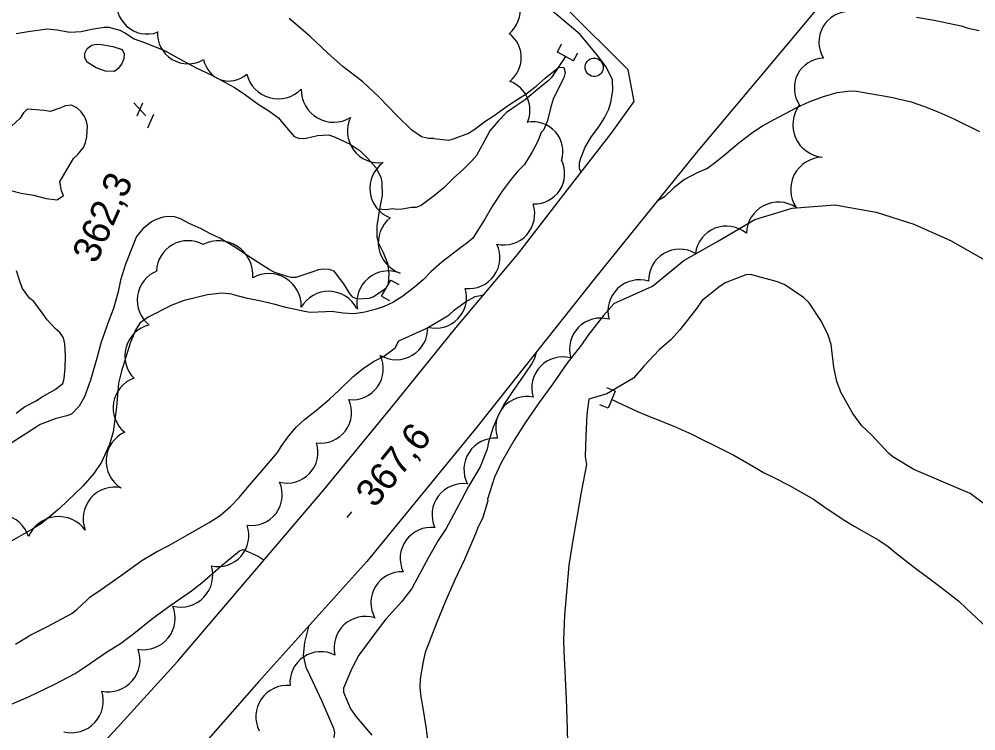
# Model space of a CAD drawing. Extents: x 287698 to 290158, y 5234163 to 5237182.
# Drawn here: x 288468 to 288572.5, y 5235628.8 to 5235706.5 of the extents above; entities that cross this region are included whole.
import ezdxf

# ---------------------------------------------------------------- set-up
doc = ezdxf.new("R2010")
doc.units = 0
for name, color, linetype in [('Niveau 19', 7, 'Continuous'), ('Niveau 2', 7, 'Continuous'), ('Niveau 21', 7, 'Continuous'), ('Niveau 26', 7, 'Continuous'), ('Niveau 3', 7, 'Continuous'), ('Niveau 36', 7, 'Continuous'), ('Niveau 4', 7, 'Continuous'), ('Niveau 44', 7, 'Continuous')]:
    doc.layers.add(name, color=color, linetype=linetype)

msp = doc.modelspace()

# ---------------------------------------------------------------- linework, layer by layer
at = {"layer": 'Niveau 19'}
msp.add_lwpolyline([(288535.15, 5235697.53), (288534.5, 5235701), (288527.62, 5235707.85), (288516.03, 5235716.32), (288501.68, 5235726.96), (288487.83, 5235737.82), (288474.98, 5235749.85), (288465.84, 5235759.9), (288456.98, 5235771.37), (288449.04, 5235782.35), (288441.52, 5235792.13)], dxfattribs=at)
at = {"layer": 'Niveau 2'}
for points in [[(288532.8, 5235699.91), (288532.14, 5235701.26), (288531.2, 5235702.52), (288529.26, 5235704.86), (288528.54, 5235705.48), (288526.2, 5235707.45)], [(288565.98, 5235706.76), (288567.92, 5235706.42), (288570.88, 5235705.81), (288571.63, 5235705.55), (288572.82, 5235705.29)], [(288513.28, 5235693.5), (288512.72, 5235693.5), (288511.94, 5235693.68), (288510.9, 5235694.4), (288509.26, 5235696), (288507.28, 5235698.06), (288505.55, 5235699.67), (288503.39, 5235701.31), (288501.73, 5235702.8), (288499.77, 5235704.67), (288497.49, 5235706.6)], [(288513.28, 5235693.5), (288514.93, 5235693.3), (288515.44, 5235693.45), (288516.99, 5235694.06), (288517.66, 5235694.44), (288518.85, 5235695.35), (288519.78, 5235695.95), (288521.54, 5235697.2), (288523.38, 5235698.39), (288524.46, 5235699.2), (288525.45, 5235700.07), (288526.94, 5235701.27), (288527.5, 5235701.25), (288527.62, 5235700.71), (288527.48, 5235700.14), (288527.18, 5235699.56), (288526.34, 5235697.81), (288526.1, 5235697.05), (288525.67, 5235695.36), (288525.25, 5235694.4), (288525.02, 5235694.17)], [(288529.39, 5235689.84), (288529.19, 5235690.18), (288529.2, 5235690.84), (288529.34, 5235691.36), (288529.81, 5235692.55), (288530.52, 5235693.72), (288531.3, 5235694.78), (288531.92, 5235695.77), (288532.39, 5235696.71), (288532.6, 5235697.48), (288532.82, 5235698.73), (288532.8, 5235699.91)], [(288543.07, 5235690.2), (288544.06, 5235690.9), (288545, 5235691.66), (288546.59, 5235693.02), (288548.13, 5235694.2), (288549.17, 5235694.87), (288550.38, 5235695.52), (288552.93, 5235696.89), (288554.34, 5235697.55), (288555.85, 5235698.1), (288557.34, 5235698.53), (288558.74, 5235698.71), (288559.43, 5235698.67), (288560.91, 5235698.43), (288563.21, 5235698.02), (288565.41, 5235697.51), (288566.88, 5235697.01), (288568.43, 5235696.39), (288570.05, 5235695.63), (288572.85, 5235694.25)], [(288525.02, 5235694.17), (288524.65, 5235693.22), (288524, 5235691.96), (288523.18, 5235690.66), (288522.46, 5235689.93), (288521.74, 5235689.06), (288520.75, 5235687.76), (288519.7, 5235686.14), (288518.86, 5235684.68), (288517.54, 5235682.63), (288517.05, 5235682.18), (288516.21, 5235681.55), (288514.18, 5235680.01), (288512.98, 5235678.93), (288512.14, 5235678.08), (288511.2, 5235677.28), (288509.92, 5235676.28), (288508.81, 5235675.6), (288507.88, 5235675.16), (288506.9, 5235674.82), (288505.77, 5235674.53), (288504.58, 5235674.35), (288503.38, 5235674.44), (288502.12, 5235674.62), (288501.51, 5235674.58), (288499.79, 5235674.5), (288499.16, 5235674.61), (288497.15, 5235675.03), (288495.96, 5235675.36), (288494.27, 5235675.77), (288492.94, 5235676.01), (288491.43, 5235676.44), (288491.43, 5235676.44)], [(288543.07, 5235690.2), (288541.96, 5235689.73), (288540.67, 5235689.03), (288539.51, 5235688.12), (288538.46, 5235687.13), (288537.68, 5235686.65)], [(288532.96, 5235675.47), (288537.15, 5235677.38), (288540.6, 5235680.16), (288544.19, 5235682.2), (288548.35, 5235684.64), (288552.4, 5235685.88), (288557.07, 5235686.26), (288561.59, 5235685.46), (288565.7, 5235684.13), (288569.7, 5235682.35), (288573.22, 5235680.35)], [(288573.56, 5235653.45), (288571.83, 5235654.73), (288569.19, 5235655.86), (288565.71, 5235657.34), (288563.39, 5235658.74), (288562.94, 5235659.15), (288561.08, 5235661.15), (288560.01, 5235662.11), (288559.04, 5235663.45), (288557.76, 5235665.74), (288557.28, 5235666.97), (288556.97, 5235668.52), (288556.69, 5235670.99), (288556.35, 5235672.03), (288555.61, 5235673.51), (288554.26, 5235675.55), (288553.66, 5235676.15), (288551.62, 5235677.53), (288550.83, 5235677.85), (288547.88, 5235678.64), (288547.37, 5235678.6), (288545.09, 5235677.72), (288544.41, 5235677.28), (288542.55, 5235675.76), (288541.99, 5235674.98), (288540.15, 5235672.61), (288539.18, 5235671.52), (288537.9, 5235670.42), (288536.22, 5235668.65), (288535.09, 5235667.32), (288532.17, 5235665.62), (288530.22, 5235665.05), (288529.99, 5235663.34), (288529.9, 5235660.99), (288529.82, 5235658.76), (288529.97, 5235657.89)], [(288491.43, 5235676.44), (288491.24, 5235676.49), (288490.14, 5235676.62), (288488.6, 5235676.43), (288486.05, 5235675.8), (288484.68, 5235675.31), (288482.12, 5235673.99), (288481.21, 5235673.33), (288480.72, 5235672.58), (288480.15, 5235671.15), (288479.18, 5235668.1), (288478.88, 5235666.78), (288478.64, 5235664.15), (288478.29, 5235661.46), (288477.89, 5235660.08), (288477.01, 5235658.15), (288476.17, 5235656.9), (288474.97, 5235655.54), (288472.42, 5235653.09), (288470.45, 5235651.45), (288469.5, 5235650.87), (288467.24, 5235649.57)], [(288509.49, 5235671.41), (288512.52, 5235672.8), (288514.98, 5235674.26), (288515.56, 5235674.78), (288516.75, 5235675.67), (288517.8, 5235676.23), (288518.74, 5235676.43)], [(288532.96, 5235675.47), (288532.94, 5235675.44), (288531.82, 5235674.17), (288530.1, 5235671.99), (288529.42, 5235670.96), (288527.83, 5235668.91), (288526.27, 5235666.69), (288524.79, 5235664.66), (288523.26, 5235662.46), (288522.07, 5235660.57), (288520.69, 5235658.16), (288519.9, 5235656.5), (288519.17, 5235654.11), (288519.19, 5235653.92)], [(288467.63, 5235638.29), (288469.3, 5235639.29), (288471.13, 5235640.19), (288473.78, 5235641.63), (288474.37, 5235642.09), (288475.37, 5235643.06), (288475.75, 5235643.4), (288476.99, 5235644.24), (288479.19, 5235645.83), (288481.43, 5235647.43), (288482.94, 5235648.34), (288484.38, 5235649.07), (288486.16, 5235650.08), (288488.78, 5235651.57), (288489.98, 5235652.33), (288491.08, 5235653.32), (288492.07, 5235654.32), (288492.94, 5235655.37), (288494.38, 5235657.04), (288496.21, 5235659.22), (288496.62, 5235659.87), (288497.45, 5235661.04), (288498.29, 5235662.02), (288499.19, 5235662.81), (288500.5, 5235663.82), (288501.92, 5235665.04), (288502.91, 5235665.97), (288504.44, 5235667.48), (288505.62, 5235668.41), (288506.79, 5235669.2), (288507.92, 5235669.77), (288509.08, 5235670.63), (288509.49, 5235671.41)], [(288524.46, 5235670.14), (288524.3, 5235669.49), (288523.98, 5235668.92), (288523.23, 5235667.79), (288522.02, 5235666.1), (288520.94, 5235664.45), (288520.28, 5235663.13), (288519.78, 5235661.98), (288519.26, 5235660.34), (288519.13, 5235659.58), (288518.34, 5235657.64)], [(288518.34, 5235657.64), (288517.08, 5235655.51), (288516.27, 5235653.96), (288514.64, 5235650.91), (288513.77, 5235649.6), (288512.72, 5235647.75), (288511.22, 5235644.97), (288510.91, 5235644.34)], [(288529.97, 5235657.89), (288529.39, 5235654.86), (288528.94, 5235652.33), (288528.5, 5235649.85), (288528.04, 5235646.91), (288527.82, 5235644.35), (288527.57, 5235641.45), (288527.45, 5235638.71), (288527.47, 5235637.5), (288527.58, 5235635.31), (288527.75, 5235632.32), (288527.8, 5235630.15), (288527.9, 5235627.63)], [(288519.19, 5235653.92), (288518.62, 5235652.01), (288518.13, 5235651.1), (288517.83, 5235650.31), (288516.66, 5235647.53), (288515.63, 5235645.36), (288514.56, 5235642.96), (288513.59, 5235640.56), (288512.33, 5235637.38), (288512.13, 5235636.4), (288511.81, 5235634.51), (288511.77, 5235633.55), (288511.88, 5235632.53), (288512.07, 5235631.49), (288512.44, 5235629.02), (288512.77, 5235626.34)], [(288465.77, 5235631.16), (288469.04, 5235632.53), (288471.83, 5235633.86), (288474.15, 5235635.06), (288475.23, 5235635.8), (288477.55, 5235637.41), (288479.08, 5235638.35), (288480.54, 5235639.43), (288482.6, 5235641.11), (288484.46, 5235642.47), (288486.85, 5235644.1), (288487.99, 5235645.02), (288489.99, 5235646.76), (288492.07, 5235648.48), (288492.49, 5235648.6), (288494.12, 5235647.89), (288494.77, 5235647.46)], [(288510.91, 5235644.34), (288509.8, 5235642.94), (288508.07, 5235641.01), (288507.18, 5235639.88), (288505.09, 5235637.08), (288504.35, 5235635.62), (288503.44, 5235633.47), (288503.45, 5235633.03), (288504.2, 5235631.2), (288504.8, 5235630.33), (288506.51, 5235628.33)], [(288499.61, 5235640.21), (288499.19, 5235638.47), (288499.03, 5235637.05), (288499.33, 5235635.77), (288499.76, 5235634.85), (288501.06, 5235632.04), (288502.33, 5235629.1), (288502.44, 5235628.59), (288502.17, 5235626.86), (288501.83, 5235624.2), (288501.88, 5235623.25), (288502.11, 5235620.09), (288501.94, 5235618.86), (288501.84, 5235618.19)]]:
    msp.add_lwpolyline(points, dxfattribs=at)
at = {"layer": 'Niveau 21'}
for points in [[(288562.24, 5235716.27), (288552.79, 5235704.84), (288541.92, 5235691.92), (288530.8, 5235678.12), (288517.95, 5235661.94), (288505.99, 5235647.29), (288494.19, 5235634.19), (288482.67, 5235621.05), (288470.98, 5235607.98), (288460.02, 5235597.36), (288450.18, 5235588.1), (288439.28, 5235579.45), (288425.79, 5235570.86), (288416.17, 5235565.9), (288404.36, 5235561.32)], [(288412.58, 5235574.13), (288418.65, 5235577.47), (288426.12, 5235581.71), (288432.71, 5235585.95), (288439.69, 5235591.35), (288445.94, 5235596.79), (288452.32, 5235602.86), (288458.5, 5235608.6), (288464.84, 5235614.72), (288470.94, 5235620.83), (288478.37, 5235628.75), (288485.32, 5235636.39), (288493.15, 5235645.55), (288501.27, 5235655.12), (288508.63, 5235664.08), (288515.68, 5235672.81), (288522.48, 5235680.85), (288527.84, 5235687.84), (288532.67, 5235694.05), (288535.15, 5235697.53)]]:
    msp.add_lwpolyline(points, dxfattribs=at)
at = {"layer": 'Niveau 26'}
for p, q in [((288526.78, 5235702.94), (288527.25, 5235703.82)), ((288528.56, 5235701.99), (288526.78, 5235702.94)), ((288528.56, 5235701.99), (288529.03, 5235702.87)), ((288507.58, 5235676.29), (288508.59, 5235678.04)), ((288508.59, 5235678.04), (288509.46, 5235677.55)), ((288507.58, 5235676.29), (288508.45, 5235675.79)), ((288533.1, 5235665.91), (288532.17, 5235666.28)), ((288533.1, 5235665.91), (288532.33, 5235664.04)), ((288532.33, 5235664.04), (288531.41, 5235664.41))]:
    msp.add_line(p, q, dxfattribs=at)
at = {"layer": 'Niveau 3'}
for p, q in [((288480.53, 5235697.38), (288481.84, 5235695.98)), ((288480.89, 5235695.97), (288481.53, 5235697.4)), ((288482.07, 5235694.68), (288482.72, 5235696.14)), ((288503.83, 5235652.11), (288504.33, 5235652.73))]:
    msp.add_line(p, q, dxfattribs=at)
at = {"layer": 'Niveau 36'}
msp.add_ellipse((288530.8, 5235701.27), major_axis=(0.994, -0.109), ratio=0.999984, dxfattribs=at)
at = {"layer": 'Niveau 4'}
for points in [[(288467.68, 5235704.95), (288469.02, 5235705.18), (288471.07, 5235705.46), (288472.16, 5235705.36), (288473.57, 5235705.12), (288474.8, 5235705.18), (288475.92, 5235705.43), (288477.3, 5235705.67), (288477.8, 5235705.65), (288479.02, 5235705.33), (288479.63, 5235704.99), (288480.58, 5235704.37), (288481.72, 5235703.97), (288483.96, 5235703.07), (288485.11, 5235702.43), (288487.34, 5235701.22), (288489.12, 5235700.38), (288491.54, 5235699.08), (288492.59, 5235698.37), (288494.1, 5235697.23), (288495.27, 5235696.52), (288496.35, 5235695.75), (288496.77, 5235695.2), (288498.03, 5235693.72), (288498.64, 5235693.48), (288499.36, 5235693.53), (288500.6, 5235693.84), (288501.84, 5235693.89), (288502.51, 5235693.63), (288504.15, 5235692.89), (288505.25, 5235692.16), (288506.1, 5235691.32), (288506.96, 5235690.32), (288507.51, 5235689.28), (288507.62, 5235688.7)], [(288477.44, 5235700.84), (288476.44, 5235701.23), (288475.44, 5235701.85), (288475.18, 5235702.32), (288475.2, 5235702.83), (288475.44, 5235703.33), (288475.97, 5235703.7), (288476.48, 5235703.81), (288477.03, 5235703.77), (288478.25, 5235703.55), (288479.27, 5235703.23), (288479.48, 5235702.73), (288479.45, 5235702.18), (288479.2, 5235701.63), (288478.83, 5235701.16), (288478.42, 5235700.8), (288477.44, 5235700.84)], [(288527.68, 5235702.46), (288526.13, 5235700.15), (288525.77, 5235699.78), (288524.82, 5235699.02), (288523.28, 5235697.73), (288522.28, 5235697.08), (288521.24, 5235696.35), (288520.31, 5235695.4), (288519.42, 5235694.33), (288518.77, 5235693.09), (288517.94, 5235691.65), (288517.42, 5235691.04), (288516.49, 5235690.12), (288515.55, 5235689.26), (288514.39, 5235688.12), (288513.35, 5235687.27), (288511.9, 5235686.18), (288511.37, 5235685.95), (288510.84, 5235685.96), (288509.82, 5235685.79), (288509.27, 5235685.73), (288508.73, 5235685.82), (288508.16, 5235685.7), (288507.6, 5235685.74), (288507.38, 5235685.79)], [(288470.97, 5235686.94), (288472.17, 5235686.8), (288472.86, 5235687.29), (288472.66, 5235687.8), (288472.48, 5235688.79), (288472.75, 5235689.29), (288473.96, 5235691.3), (288474.38, 5235691.71), (288475.04, 5235692.53), (288475.27, 5235693.07), (288475.41, 5235693.69), (288475.48, 5235694.88), (288475.38, 5235695.38), (288475.17, 5235695.9), (288474.8, 5235696.41), (288474.32, 5235696.85), (288473.74, 5235697.13), (288473.04, 5235697.05), (288472.58, 5235696.85), (288471.39, 5235696.46), (288470.76, 5235696.57), (288468.89, 5235696.71), (288468.5, 5235696.3), (288468.13, 5235695.73), (288467.19, 5235694.83)], [(288507.62, 5235688.7), (288507.64, 5235687.29), (288507.51, 5235686.55), (288507.38, 5235685.79)], [(288466.96, 5235687.84), (288468.24, 5235687.54), (288469.59, 5235687.3), (288470.97, 5235686.94)], [(288507.38, 5235685.79), (288507.06, 5235683.95), (288507.07, 5235682.76), (288507.23, 5235682.15), (288507.76, 5235681.06), (288508.23, 5235679.9), (288508.39, 5235678.76), (288508.31, 5235677.64), (288508.08, 5235677.16), (288507.64, 5235676.81), (288506.71, 5235676.21), (288506.22, 5235676.04), (288504.97, 5235675.96), (288504.44, 5235676.18), (288504.08, 5235676.62), (288503.46, 5235677.63), (288502.4, 5235679.02), (288501.87, 5235679.18), (288501.29, 5235679.23), (288500.69, 5235679.16), (288500.07, 5235678.93), (288498.24, 5235678.32), (288497.73, 5235678.32), (288497.16, 5235678.45), (288495.92, 5235678.86), (288495.31, 5235679.21), (288493.33, 5235680.45), (288491.65, 5235681.59), (288489.93, 5235682.62), (288488.9, 5235683.09), (288487.88, 5235683.64), (288486.59, 5235684.21), (288485.64, 5235684.73), (288484.98, 5235684.94), (288484.26, 5235684.97), (288483.73, 5235684.89), (288482.97, 5235684.67), (288482.47, 5235684.39), (288481.52, 5235683.65), (288480.84, 5235682.78), (288480.55, 5235682.08), (288479.64, 5235679.78), (288479.1, 5235678.03), (288478.84, 5235676.77), (288478.33, 5235674.93), (288477.83, 5235673.63), (288476.95, 5235671.14), (288476.57, 5235669.77), (288475.82, 5235667.1), (288475.15, 5235665.3), (288474.57, 5235664.28), (288473.75, 5235663.41), (288473.22, 5235663.22), (288471.97, 5235662.89), (288470.32, 5235662.27), (288469.76, 5235661.9), (288467.14, 5235660.23)], [(288467.68, 5235663.51), (288468.59, 5235664.21), (288469.87, 5235664.85), (288470.47, 5235665.25), (288471.94, 5235666.08), (288472.8, 5235666.74), (288472.94, 5235667.29), (288473.05, 5235668.46), (288473.08, 5235669.74), (288473.01, 5235671.07), (288472.86, 5235671.72), (288472.46, 5235672.31), (288471.97, 5235672.75), (288471.07, 5235673.69), (288470.65, 5235674.33), (288469.62, 5235675.68), (288469.16, 5235676.05), (288468.37, 5235677.13), (288468.12, 5235677.81), (288467.74, 5235679.04)], [(288532.72, 5235664.98), (288535.6, 5235663.66), (288537.21, 5235662.98), (288539.49, 5235662.07), (288541.45, 5235661.22), (288542.52, 5235660.65), (288543.79, 5235660.05), (288546.03, 5235658.9), (288547.69, 5235657.97), (288549.36, 5235657), (288550.43, 5235656.48), (288552.04, 5235655.63), (288554.75, 5235654.11), (288555.88, 5235653.32), (288557.97, 5235651.89), (288559.2, 5235651.18), (288561.88, 5235649.63), (288562.9, 5235648.94), (288563.8, 5235648.18), (288565.77, 5235646.65), (288567.18, 5235645.6), (288568.63, 5235644.49), (288570.6, 5235642.96), (288571.44, 5235642.18), (288573.62, 5235640.14)]]:
    msp.add_lwpolyline(points, dxfattribs=at)
at = {"layer": 'Niveau 44'}
for centre, radius, start, end in [((288550.91, 5235683.05), 3.5, 56.6509, 178.3246), ((288545.24, 5235680.51), 3.42, 50.5015, 172.6743), ((288540.14, 5235678.01), 3.4, 59.8773, 181.6205), ((288509.18, 5235672.8), 3.46, 239.7314, 1.6121), ((288504.39, 5235668.35), 3.38, 263.5877, 25.6976), ((288497.28, 5235630.35), 3.42, 84.7811, 206.7242)]:
    msp.add_arc(centre, radius, start, end, dxfattribs=at)
for centre, major_axis, ratio, start_param, end_param in [((288519.41, 5235707.46), (3.27, 0.5), 0.987646, 5.251622, 7.352964), ((288482.01, 5235708.26), (2.48, -2.26), 0.999936, 3.636394, 5.788384), ((288558.69, 5235704.02), (-2.93, 1.64), 0.997186, 5.215167, 7.341648), ((288486.46, 5235705.01), (2.87, -1.74), 0.999936, 3.635063, 5.789715), ((288519.48, 5235702.33), (3.32, -0.54), 0.984731, 5.543715, 7.358073), ((288491.19, 5235703.31), (-1.16, -3.4), 0.855086, 5.339348, 7.233514), ((288555.98, 5235698.97), (-3, 1.47), 0.989019, 5.208817, 7.323024), ((288496.3, 5235701.36), (-1.14, -3.34), 0.998888, 5.278509, 7.404218), ((288520.44, 5235696.58), (-2.09, 2.62), 0.999936, 3.634934, 5.260467), ((288502.36, 5235698.82), (3.55, 0.04), 0.999995, 3.1132, 5.245537), ((288556.21, 5235695.08), (-3.44, -1.49), 0.966226, 5.254633, 7.319239), ((288507.31, 5235694.29), (3.45, -0.18), 0.998915, 2.745778, 4.899888), ((288524.05, 5235692), (2.8, 1.85), 0.983714, 5.415499, 7.436511), ((288524.24, 5235689.68), (2.93, -1.61), 0.996113, 5.183601, 7.231823), ((288555.81, 5235687.91), (-3.17, 1.63), 0.995029, 5.214736, 7.337639), ((288509.76, 5235688.05), (0.82, -3.35), 0.999128, 3.514675, 5.673132), ((288520.91, 5235685.27), (2.54, -2.27), 0.996451, 5.218805, 7.333847), ((288510.75, 5235682.12), (-3.46, -0.64), 0.998284, 5.215857, 7.339982), ((288486.45, 5235678.9), (-2.88, -1.88), 0.999864, 3.633316, 5.661844), ((288489.8, 5235678.6), (2.41, 2.85), 0.999732, 5.33249, 7.460791), ((288517.11, 5235680.5), (2.77, -1.97), 0.998719, 5.218803, 7.344354), ((288484.35, 5235675.84), (0.16, -3.44), 0.998957, 3.471606, 5.57131), ((288495.27, 5235675.21), (2.13, 2.83), 0.99962, 5.31627, 7.444864), ((288508.34, 5235675.59), (-2.63, -2.23), 0.999256, 3.63491, 5.789868), ((288535.74, 5235674.63), (-2.39, 2.47), 0.998397, 5.216263, 7.344382), ((288501.81, 5235673.36), (-3.45, 0.08), 0.999939, 3.635032, 5.789746), ((288513.48, 5235676.18), (2.47, -2.34), 0.993767, 5.215722, 7.327086), ((288531.51, 5235670.48), (-2.44, 2.39), 0.995883, 5.214214, 7.33916), ((288483.02, 5235669.76), (-3.25, 1.19), 0.999272, 5.296525, 7.418462), ((288527.39, 5235666.24), (-2.39, 2.44), 0.996332, 5.253449, 7.373635), ((288481.7, 5235664.09), (-3.38, 0.58), 0.998747, 5.218081, 7.347383), ((288500.93, 5235663.6), (2.43, -2.35), 0.999754, 5.349431, 7.477683), ((288523.46, 5235661.91), (-2.54, 2.29), 0.994755, 5.245094, 7.359149), ((288480.97, 5235658.28), (-2.85, -1.96), 0.99714, 4.53456, 6.68824), ((288519.99, 5235657.36), (-2.86, 1.86), 0.99995, 5.216213, 7.345735), ((288497.26, 5235659.24), (2.42, -2.37), 0.995, 5.24593, 7.365092), ((288478.46, 5235651.98), (-2.23, -2.64), 0.999255, 3.636146, 5.788632), ((288493.36, 5235654.61), (2.67, -2.09), 0.994678, 5.240427, 7.359661), ((288516.52, 5235652.39), (-2.75, 2.04), 0.997025, 5.217054, 7.336768), ((288465.72, 5235648.95), (0.67, 3.44), 0.999233, 5.218109, 7.34552), ((288472.34, 5235648.63), (-0.25, 3.57), 0.998242, 5.262691, 7.384235), ((288489.72, 5235650.13), (2.54, -2.23), 0.999948, 5.217724, 7.342759), ((288513.04, 5235647.62), (-2.75, 2.04), 0.994397, 5.243503, 7.358058), ((288485.68, 5235645.81), (2.52, -2.4), 0.999219, 5.218762, 7.341955), ((288509.85, 5235642.78), (-2.95, 1.75), 0.993486, 5.216243, 7.327755), ((288481.59, 5235641.14), (2.71, -2.17), 0.99804, 5.218692, 7.345263), ((288505.82, 5235637.88), (-2.36, 2.49), 0.994253, 5.215589, 7.331405), ((288477.75, 5235636.54), (2.49, -2.42), 0.998851, 5.27834, 7.402191), ((288500.99, 5235634.04), (-1.95, 2.81), 0.994231, 5.213902, 7.33195), ((288473.73, 5235632.09), (2.54, -2.38), 0.999805, 5.220516, 7.346048)]:
    msp.add_ellipse(centre, major_axis=major_axis, ratio=ratio, start_param=start_param, end_param=end_param, dxfattribs=at)

# ---------------------------------------------------------------- texts
at = {"layer": 'Niveau 3'}
for s, rotation, p in [('362,3', 66.1217, (288476.44, 5235679.71)), ('367,6', 50.9026, (288506.85, 5235653.05))]:
    msp.add_text(s, height=3, rotation=rotation, dxfattribs=at).set_placement(p)

doc.saveas('drawing.dxf')
